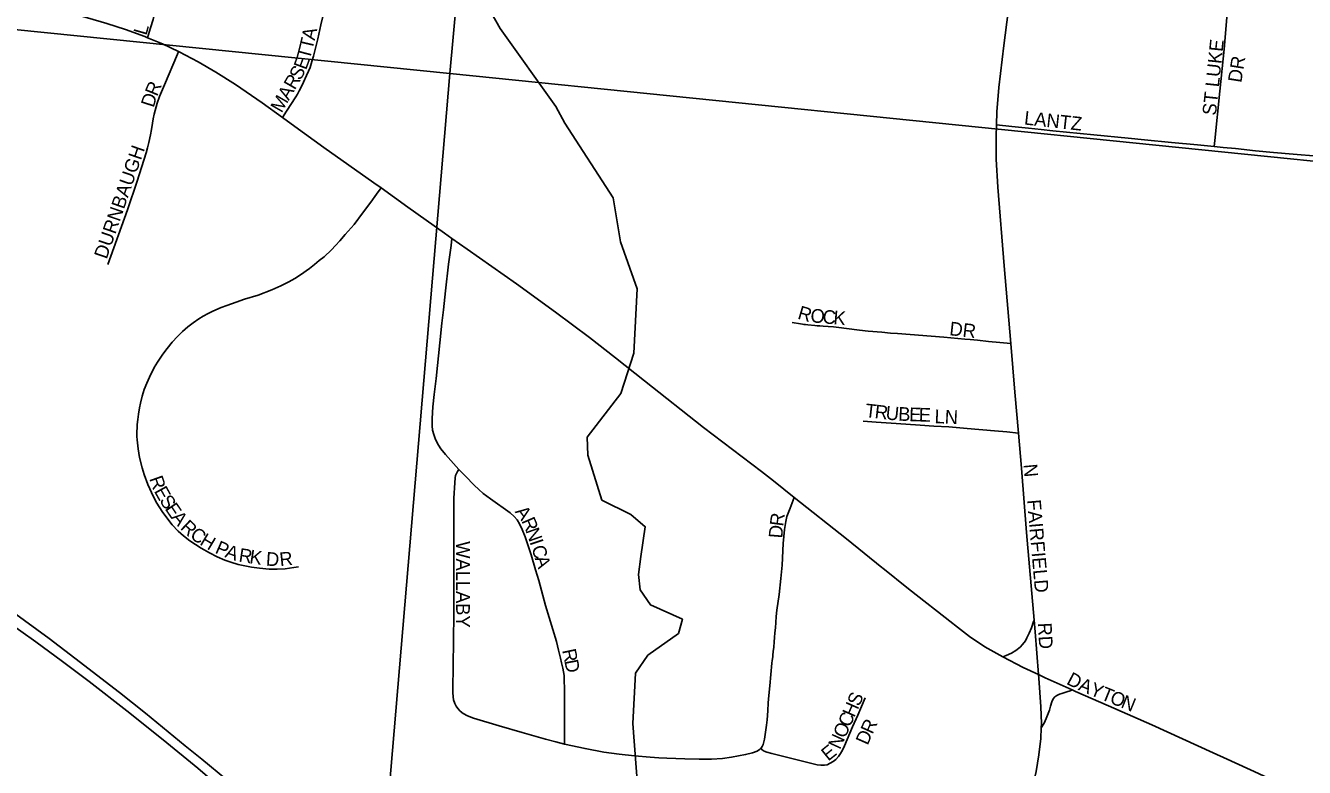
# Model space of a CAD drawing. Extents: x 1410790 to 1770854, y 448063 to 770588.
# Drawn here: x 1526843 to 1531514, y 632789 to 635499 of the extents above; entities that cross this region are included whole.
import ezdxf

# ---------------------------------------------------------------- set-up
doc = ezdxf.new("R2010")
doc.units = 0
for name, color, linetype in [('GM_X_City_Street', 7, 'Continuous'), ('GM_X_City_Street_Text', 7, 'Continuous'), ('GM_X_Minor_River', 7, 'Continuous'), ('GM_X_Section', 7, 'Continuous'), ('GM_X_US_Route', 7, 'Continuous')]:
    doc.layers.add(name, color=color, linetype=linetype)

msp = doc.modelspace()

# ---------------------------------------------------------------- linework, layer by layer
at = {"layer": 'GM_X_City_Street'}
for points in [[(1527288.3, 635454.9), (1527299.1, 635490.5), (1527308.5, 635521.4), (1527314.8, 635546.5), (1527323.6, 635594.3), (1527329.7, 635632.8), (1527331.6, 635648.8), (1527336.1, 635681), (1527342, 635722.9), (1527347.3, 635761.4), (1527349.2, 635777.4)], [(1527781.4, 635163.5), (1527796, 635186.2), (1527829.8, 635238.6), (1527835.9, 635249), (1527842.7, 635260.9), (1527850.1, 635274.3), (1527858.5, 635292.5), (1527869.6, 635317.1), (1527876.7, 635332.6), (1527881.9, 635346.7), (1527889.1, 635367.9), (1527894.5, 635387.4), (1527910.3, 635451.1), (1527921.2, 635502.4), (1527932.2, 635547), (1527939.8, 635568.6), (1527948, 635587.4), (1527960.8, 635608.6), (1527969.6, 635620.4), (1527979.7, 635632.8), (1527994, 635648.1)], [(1526904.5, 635573.8), (1526938.3, 635564.1), (1527069.3, 635528.1), (1527140.3, 635507.1), (1527208.3, 635485.1), (1527278.3, 635459.1), (1527288.3, 635454.9)], [(1530389.2, 635137), (1530390.8, 635183.7), (1530398, 635272.8), (1530416.1, 635426.5), (1530431.9, 635549.8)], [(1531185, 635057.2), (1531187.3, 635079.5), (1531205.2, 635259.2), (1531220.6, 635412.8), (1531232.1, 635543.7), (1531233.4, 635558)], [(1527288.3, 635454.9), (1527343.3, 635432.1), (1527402.1, 635404.2)], [(1527143.5, 634626.6), (1527215.5, 634825.7), (1527250.6, 634931.3), (1527283.4, 635034.2), (1527288.6, 635053.2), (1527293.3, 635072.2), (1527298.8, 635099.8), (1527302.3, 635119.8), (1527306.1, 635143.3), (1527308.9, 635158.7), (1527312.6, 635175), (1527323.8, 635216), (1527332.6, 635240.6), (1527350.5, 635282.8), (1527398.3, 635395.3), (1527402.1, 635404.2)], [(1527402.1, 635404.2), (1527404.3, 635403.1), (1527473.5, 635366.6), (1527538.4, 635329.3), (1527609.9, 635283.8), (1527707.1, 635217.4), (1527781.4, 635163.5)], [(1527781.4, 635163.5), (1527826.4, 635130.9), (1527932.6, 635053.7), (1528114.8, 634925.3), (1528141.6, 634906)], [(1530441.6, 634337.6), (1530417.9, 634621.3), (1530394.1, 634909.2), (1530388.4, 635011.5), (1530387.7, 635094.3), (1530389.2, 635137)], [(1530389.2, 635137), (1530444.9, 635130.9), (1530506.8, 635124), (1530552.5, 635119.3), (1530594.8, 635114.9), (1530745, 635100.2), (1530870.6, 635087.8), (1530929.7, 635082), (1531028.5, 635072.5), (1531123.5, 635063.4), (1531185, 635057.2)], [(1531185, 635057.2), (1531217.4, 635053.9), (1531262, 635049.7), (1531336, 635041.9), (1531401.3, 635036.1), (1531473.2, 635029.9), (1531561.6, 635022.5), (1531660, 635012.5), (1531823.4, 634995.6), (1531973.4, 634979.4), (1532026.2, 634974.1), (1532105.9, 634965.9), (1532192.9, 634956.8), (1532266.8, 634949.3), (1532325, 634943.6), (1532400.6, 634935.9), (1532459.5, 634930.4), (1532567.1, 634919.2), (1532687.7, 634905.8), (1532689.2, 634905.7)], [(1527839.4, 633522.2), (1527823.4, 633519.2), (1527791.2, 633514.8), (1527762.1, 633513.2), (1527732.9, 633513.7), (1527697.3, 633516.5), (1527668.3, 633520.6), (1527644.2, 633525.2), (1527619.6, 633530.2), (1527592.3, 633538.1), (1527571.2, 633545.9), (1527542.7, 633558.5), (1527515, 633572.4), (1527483.9, 633589.4), (1527443.5, 633617.1), (1527420.3, 633634.8), (1527400.9, 633651.8), (1527378.8, 633675.4), (1527358.3, 633700.6), (1527341.4, 633724.4), (1527322.5, 633754.8), (1527310.2, 633777.6), (1527289.9, 633822.1), (1527275.9, 633858.5), (1527268.2, 633883.2), (1527259.4, 633921.3), (1527254.3, 633953.3), (1527250.6, 633985.4), (1527249.8, 633998.1), (1527249.5, 634016.3), (1527250, 634029.3), (1527250.8, 634041.6), (1527253, 634060.2), (1527255.2, 634079.8), (1527258.8, 634102.5), (1527262.1, 634120.1), (1527268.3, 634145.1), (1527276.5, 634169.8), (1527285.8, 634193.3), (1527295.8, 634214.5), (1527313, 634249.4), (1527324.5, 634268.9), (1527344.5, 634298.5), (1527359.8, 634319.5), (1527378, 634342.1), (1527397.6, 634363.6), (1527416.4, 634382.1), (1527435.2, 634398.1), (1527454.9, 634412.9), (1527475.9, 634427.6), (1527492, 634437.4), (1527510, 634446.7), (1527524.2, 634454.3), (1527537.3, 634460.3), (1527556.9, 634469.1), (1527577.8, 634476.7), (1527611.6, 634488.9), (1527642.7, 634499.1), (1527693, 634514.7), (1527742.1, 634533.2), (1527775.4, 634547.9), (1527805.1, 634563.2), (1527826.3, 634575.3), (1527847.4, 634589.1), (1527879.9, 634612), (1527898.7, 634626.5), (1527915.9, 634640.4), (1527933.5, 634654.8), (1527960.3, 634679.9), (1527975.6, 634695.5), (1527991.2, 634712.7), (1528010.8, 634736.1), (1528043, 634772.8), (1528073.2, 634813.6), (1528103.5, 634854.6), (1528125.1, 634883.7), (1528141.6, 634906)], [(1528141.6, 634906), (1528239.8, 634835.5), (1528373.1, 634740.2), (1528400.3, 634721.4)], [(1528425.7, 633877.4), (1528376.7, 633932), (1528360.1, 633952.3), (1528350.9, 633966), (1528340.4, 633986.3), (1528333.6, 634004.8), (1528329.9, 634020.7), (1528328.2, 634036.9), (1528328.3, 634063.1), (1528330.7, 634105.7), (1528335.5, 634151.4), (1528342.3, 634210.1), (1528356.7, 634340.5), (1528363.3, 634412.3), (1528369.2, 634461.2), (1528377.2, 634529.6), (1528387.9, 634627.4), (1528397, 634696.1), (1528400.3, 634721.4)], [(1528400.3, 634721.4), (1528456.4, 634682.6), (1528635.7, 634555.6), (1528779.2, 634452), (1528902.5, 634359.7), (1528998.2, 634285.2), (1529103.2, 634201.2), (1529319.8, 634030.9), (1529531.4, 633870.1), (1529575, 633835.7), (1529651, 633775.1)], [(1529642.6, 634414.3), (1529673.4, 634409.2), (1529680.8, 634408), (1529686.2, 634407.2), (1529691.8, 634406.5), (1529700.4, 634405.4), (1529725.3, 634403.1), (1529734.5, 634402.4), (1529743.8, 634401.9), (1529755.8, 634401.4), (1529774.9, 634399.9), (1529794.4, 634398.4), (1529804.1, 634397.4), (1529888.7, 634386.8), (1529921.3, 634383.2), (1529970.1, 634378.7), (1530002.2, 634376), (1530028.1, 634374.7), (1530196.7, 634360.4), (1530274.3, 634353.5), (1530293.8, 634351.9), (1530319.9, 634349.3), (1530360.1, 634345.5), (1530402.2, 634341.4), (1530441.6, 634337.6)], [(1530469.3, 634010.4), (1530456.5, 634160.4), (1530441.6, 634337.6)], [(1529902.6, 634053.8), (1529949.9, 634050.5), (1530023.2, 634045.5), (1530111, 634039.6), (1530160.7, 634036.2), (1530215.4, 634032.8), (1530282.6, 634027.1), (1530382.6, 634018.4), (1530427.5, 634014.3), (1530469.3, 634010.4)], [(1530526.7, 633326.7), (1530499.5, 633647.2), (1530480.3, 633882.6), (1530469.3, 634010.4)], [(1528425.7, 633877.4), (1528421, 633869.8), (1528416.7, 633862.5), (1528413.6, 633855.6), (1528411.7, 633846.3), (1528410.6, 633828.6), (1528407.7, 633773), (1528407.1, 633682.6), (1528407.6, 633541.8), (1528407.5, 633349.1), (1528405.2, 633159.1), (1528403.4, 633075.8), (1528403.2, 633062.4), (1528404.4, 633046.6), (1528406.3, 633035.1), (1528410.6, 633021.9), (1528415.2, 633012.4), (1528421.3, 633003.9), (1528430.9, 632993.8), (1528441.8, 632985.3), (1528456.8, 632977), (1528478.8, 632968.6), (1528572.7, 632940.8), (1528657.2, 632915.8), (1528741.6, 632892.3), (1528779.4, 632881.8), (1528811.1, 632874.2), (1528811.3, 632874.2)], [(1528811.3, 632874.2), (1528811.4, 632988), (1528811.7, 633041.3), (1528811.7, 633076), (1528810.8, 633108.1), (1528809.9, 633124.9), (1528808.4, 633137.8), (1528805.7, 633151.5), (1528801, 633171.4), (1528797.1, 633188.2), (1528790, 633217), (1528781.8, 633249.3), (1528742.6, 633380.8), (1528717.6, 633471.1), (1528705.9, 633510.7), (1528689.5, 633565.8), (1528678.9, 633598.3), (1528667.7, 633630.9), (1528657.1, 633658.4), (1528646.9, 633679), (1528638.2, 633692.9), (1528627.7, 633705.6), (1528613.2, 633718.8), (1528541.2, 633770.5), (1528527.8, 633780), (1528514.8, 633789.8), (1528498.6, 633803.9), (1528481, 633820.5), (1528449.5, 633852.4), (1528431.4, 633871), (1528425.7, 633877.4)], [(1529527.9, 632857.3), (1529529.8, 632859), (1529534, 632865.2), (1529536.9, 632871.9), (1529541.8, 632891.6), (1529545.9, 632917.6), (1529549.4, 632943.5), (1529551.7, 632963.1), (1529553.9, 632996), (1529555.4, 633025.2), (1529557.5, 633050.9), (1529561, 633086.4), (1529569.4, 633169.9), (1529570.5, 633179.5), (1529572, 633192.4), (1529572.6, 633198.9), (1529574, 633211.8), (1529575.6, 633228), (1529577.5, 633247.5), (1529578.9, 633263.7), (1529580.3, 633279.9), (1529581.8, 633299.3), (1529583, 633318.4), (1529584.9, 633340.3), (1529587.7, 633362.8), (1529595.1, 633420.6), (1529601.7, 633479), (1529606.3, 633528), (1529610.6, 633606.5), (1529615.3, 633658.2), (1529619.6, 633686.9), (1529624.2, 633705.5), (1529635.8, 633735.6), (1529651, 633775.1)], [(1529651, 633775.1), (1529841.3, 633623.4), (1529970.8, 633519.6)], [(1529970.8, 633519.6), (1529974.2, 633516.9), (1530067.8, 633441.4), (1530229.8, 633314.1)], [(1530229.8, 633314.1), (1530235.5, 633309.6), (1530291, 633267.6), (1530346.4, 633229.9), (1530401.2, 633198.3), (1530413.1, 633192.2)], [(1530413.1, 633192.2), (1530425, 633197.4), (1530444.4, 633206.7), (1530459.8, 633216.5), (1530475.5, 633228.5), (1530484.9, 633238.2), (1530495, 633251.6), (1530500.4, 633261.7), (1530508.7, 633279.1), (1530516.8, 633299.3), (1530523.8, 633318.6), (1530526.7, 633326.7)], [(1530543.1, 633127.9), (1530530.3, 633284.3), (1530526.7, 633326.7)], [(1530413.1, 633192.2), (1530486.7, 633154.4), (1530543.1, 633127.9)], [(1530552.7, 632933.5), (1530553.4, 632949.2), (1530551.7, 633010.2), (1530544.2, 633114.3), (1530543.1, 633127.9)], [(1530543.1, 633127.9), (1530567.2, 633116.6), (1530665.9, 633071.7)], [(1530552.7, 632933.5), (1530563.4, 632950.4), (1530570.7, 632967.9), (1530578.3, 632986.3), (1530582.5, 632998.4), (1530586.4, 633012.3), (1530591.1, 633028), (1530596.7, 633039.7), (1530602.1, 633046.3), (1530610, 633052), (1530619.7, 633056.5), (1530628, 633059.2), (1530646.5, 633065), (1530658.1, 633069), (1530665.9, 633071.7)], [(1530665.9, 633071.7), (1530677.7, 633066.4), (1530798.2, 633014.3), (1530957.3, 632944.7), (1531180.8, 632842.2)], [(1529527.9, 632857.3), (1529534.1, 632852.6), (1529541, 632848.3), (1529551, 632844.5), (1529569.1, 632839.5), (1529734.3, 632798.3), (1529747.8, 632796.4), (1529760.1, 632796.4), (1529770.9, 632798.7), (1529782.4, 632803.7), (1529792.5, 632810.1), (1529802.2, 632817.7), (1529812.7, 632829.2), (1529819.6, 632839.2), (1529826.7, 632851.4), (1529834.8, 632867.6), (1529863.5, 632937.3), (1529882.5, 632979.1), (1529910.1, 633043.2)], [(1530403.6, 632419.2), (1530430.4, 632479), (1530480.5, 632595.8), (1530500, 632647), (1530519.3, 632711.6), (1530534.4, 632774.2), (1530544.7, 632834.2), (1530551.2, 632894.8), (1530552.7, 632933.5)], [(1528811.3, 632874.2), (1528886.5, 632857.6), (1528955, 632844.9), (1528983.1, 632840.6), (1529010.8, 632837.2), (1529067.1, 632831), (1529124.8, 632826.4), (1529156, 632824.3), (1529185.2, 632822.9), (1529250.5, 632819.7), (1529302.9, 632818.6), (1529349, 632818.6), (1529388.5, 632821.6), (1529421.3, 632826), (1529473, 632835.7), (1529498.8, 632842.3), (1529514.8, 632848.4), (1529524.2, 632853.9), (1529527.9, 632857.3)], [(1531180.8, 632842.2), (1531232.1, 632818.7), (1531347, 632766.8), (1531459.7, 632712.7), (1531543.8, 632673.1)]]:
    msp.add_lwpolyline(points, dxfattribs=at)
at = {"layer": 'GM_X_Minor_River'}
msp.add_lwpolyline([(1529078.6, 632723.9), (1529060.9, 632948.9), (1529070.4, 633133.2), (1529115.7, 633198.4), (1529227.4, 633278.1), (1529242.4, 633329.9), (1529125.2, 633382.7), (1529088.2, 633437.6), (1529081.3, 633493.9), (1529090.6, 633559.9), (1529106.6, 633667.8), (1529053.4, 633713.1), (1528948.3, 633765.6), (1528897.3, 633929.1), (1528894.6, 633995.4), (1529017.8, 634155.1), (1529064.6, 634302.4), (1529077.1, 634536.8), (1529016.3, 634708.6), (1528989.3, 634869.6), (1528812.3, 635142.2), (1528779.4, 635203.1), (1528576.5, 635488.3), (1528411.8, 635780.8)], dxfattribs=at)
at = {"layer": 'GM_X_Section'}
for points in [[(1528881.3, 640647.9), (1528392.9, 635323.7), (1523175.4, 635852.3), (1523663.4, 641153)], [(1534160.3, 640098.2), (1533718.1, 634783.3), (1528392.9, 635323.7), (1528881.3, 640647.9)], [(1523175.4, 635852.3), (1528392.9, 635323.7), (1527942.6, 630003), (1522667.1, 630530.5)], [(1528392.9, 635323.7), (1533718.1, 634783.3), (1533261.2, 629430.7), (1527942.6, 630003)]]:
    msp.add_lwpolyline(points, close=True, dxfattribs=at)
at = {"layer": 'GM_X_US_Route'}
for points in [[(1526793.9, 633358.9), (1526928.5, 633259.5), (1527022.7, 633188.4), (1527186.2, 633062.1), (1527281.2, 632986.7), (1527425.6, 632867.9), (1527486.8, 632818.3), (1527578.1, 632743.5)], [(1526758.3, 633334.1), (1526770.6, 633325.7), (1526880.4, 633247.9), (1526978.2, 633175.9), (1527075.1, 633102.7), (1527212.5, 632996), (1527345.6, 632889.3), (1527472.7, 632785.4), (1527550.2, 632719.4), (1527572, 632700.3), (1527710.7, 632578.9), (1527842.4, 632460.4), (1527888.3, 632418.1), (1527928.9, 632379.8), (1527979.2, 632332.8), (1528055, 632260.2), (1528177, 632141), (1528298.4, 632021.2), (1528401, 631919.7), (1528447.6, 631873.4), (1528493.8, 631827.5)]]:
    msp.add_lwpolyline(points, dxfattribs=at)

# ---------------------------------------------------------------- texts
at = {"layer": 'GM_X_City_Street_Text'}
for s, rotation, p in [('L', 74.2272, (1527284.2, 635461.3)), ('T', 76.8449, (1527890.5, 635408.3)), ('A', 77.1982, (1527898.6, 635442.9)), ('ST LUKE', 83.9908, (1531190.9, 635169.3)), ('T', 75.1668, (1527881.1, 635372.7)), ('S', 60.0602, (1527845.9, 635295.9)), ('E', 69.7472, (1527867.4, 635334.7)), ('DR', 81.0271, (1531283.8, 635288.6)), ('R', 60.0774, (1527826.2, 635261.6)), ('R', 67.7295, (1527323.4, 635238.1)), ('A', 60.0787, (1527804.2, 635223.4)), ('D', 72.2666, (1527310.4, 635197.2)), ('M', 60.0687, (1527777.9, 635177.7)), ('LANTZ', 353.7957, (1530488.8, 635137.9)), ('DURNBAUGH', 70.9525, (1527139, 634643.4)), ('R', 343.6776, (1529660.1, 634428.8)), ('O', 354.474, (1529708.2, 634415.8)), ('C', 355.2402, (1529752.7, 634411.5)), ('K', 355.23, (1529792.2, 634408.2)), ('DR', 353.6631, (1530215.7, 634368.1)), ('T', 353.4833, (1529907.8, 634068.9)), ('R', 353.4997, (1529942.7, 634064.9)), ('U', 354.4263, (1529983, 634060.3)), ('B', 357.4871, (1530029.6, 634055.9)), ('E', 358.0473, (1530069.7, 634054.1)), ('E', 358.0473, (1530104.9, 634052.9)), ('LN', 357.1392, (1530162.3, 634046.9)), ('N', 275.2429, (1530487.9, 633895.5)), ('R', 289.533, (1527294, 633844)), ('E', 298.922, (1527310.9, 633798.5)), ('S', 303.2639, (1527330.1, 633764.1)), ('FAIRFIELD', 274.9391, (1530501.1, 633765.6)), ('E', 304.4236, (1527350, 633733.8)), ('A', 309.0327, (1527372.5, 633701.2)), ('A', 306.1399, (1528628.9, 633722.7)), ('R', 82.5466, (1529610.3, 633667.7)), ('R', 316.7177, (1527405.2, 633661.7)), ('R', 293.3819, (1528653.4, 633689.7)), ('D', 85.4378, (1529606.9, 633624.5)), ('C', 324.8683, (1527440.1, 633629.6)), ('H', 329.2805, (1527476, 633604.5)), ('N', 289.451, (1528668.8, 633654.2)), ('I', 288.428, (1528683.3, 633612.9)), ('P', 336.3911, (1527531.8, 633573.4)), ('A', 341.144, (1527568.2, 633557.6)), ('R', 351.4889, (1527619.4, 633541)), ('K', 351.5631, (1527658.7, 633535.2)), ('D', 356.3506, (1527719.8, 633526.3)), ('R', 5.9527, (1527772.9, 633523.7)), ('WALLABY', 270, (1528415.7, 633615.2)), ('C', 287.1179, (1528690.2, 633592.3)), ('A', 288.3774, (1528702.2, 633553.4)), ('RD', 273.011, (1530540.7, 633316.4)), ('R', 281.898, (1528802.7, 633216.8)), ('D', 280.9606, (1528810.8, 633178.2)), ('D', 332.1397, (1530641.9, 633095.2)), ('A', 337.0848, (1530685, 633072.7)), ('S', 66.1503, (1529887.7, 633008.9)), ('Y', 338.0038, (1530726.4, 633055.2)), ('T', 337.9855, (1530767.2, 633038.7)), ('O', 337.9827, (1530799.8, 633025.5)), ('H', 66.1399, (1529869.9, 632968.7)), ('N', 338.0038, (1530840.6, 633009)), ('C', 66.1357, (1529853.9, 632932.5)), ('O', 66.1075, (1529836, 632892.2)), ('D', 66.0453, (1529918.6, 632867.2)), ('R', 65.6947, (1529936.5, 632907.4)), ('N', 65.4866, (1529817.5, 632851.6)), ('E', 38.9713, (1529774.8, 632809.7))]:
    msp.add_text(s, height=50, rotation=rotation, dxfattribs=at).set_placement(p)

doc.saveas('drawing.dxf')
